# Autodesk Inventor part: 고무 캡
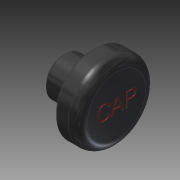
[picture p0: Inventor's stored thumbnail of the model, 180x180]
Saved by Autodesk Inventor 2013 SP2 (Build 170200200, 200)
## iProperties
Created: 2017-06
Part Number: 고무 캡
Material: 고무
Document SubType Name: Modeling
Designer: mduedu
Density: 1 g/cm^3
Author: mduedu
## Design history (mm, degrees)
sketch "스케치1"
  geometry: L1 (0, 0)-(11, 0); L2 (11, 0)-(11, 8); L3 (11, 8)-(6.5, 8); L4 (0, 4)-(0, 0); L5 (0, 4)-(6, 4); L6 (6, 4)-(6, 7.5); L7 (6, 7.5)-(6.5, 7.5); L8 (6.5, 7.5)-(6.5, 8)
  constraints: 16 end point, 2 horizontal, 2 parallel, 2 perpendicular, 2 point on line, 1 vertical
  dimensions: "d0" = 16 diameter of L3 L1; "d2" = 8 diameter of L5 L1; "d6" = 5 distance between parallel lines of L2 L6; "d7" = 0.5 distance between parallel lines of L8 L6; "d8" = 15 diameter of L7 L1; "d9" = 6 distance between parallel lines of L6 L4
revolve "회전1" sketch "스케치1" stored, may be unused: angle "d10" = 90 deg
hole "구멍1" diameter "d22" = 5; stored, may be unused: countersink angle "d26" = 90 deg, drill point angle "d28" = 0 deg; dims "d23" = 6, "d24" = 4, "d25" = 2, "d27" = 6, "d30" = 10, "d31" = 10
chamfer "모따기1" distance "d13" = 0.5; stored, may be unused: second distance "d14" = 2, angle "d15" = 45 deg
fillet "모깎기3" dims "d29" = 1
fillet "모깎기1" dims "d16" = 0.1
fillet "모깎기2" dims "d17" = 2
sketch "스케치3"
  geometry: 2 further points
  constraints: 1 coincident, 1 other
feature "엠보싱1" sketch "스케치3" dims "d18" = 0.2, "d19" = 0
node "솔리드1"
